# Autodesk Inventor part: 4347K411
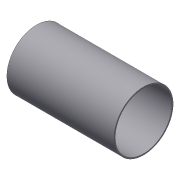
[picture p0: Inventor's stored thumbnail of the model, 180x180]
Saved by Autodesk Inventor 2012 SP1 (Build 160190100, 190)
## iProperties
Created: 2012-02
Part Number: 4347K411
Material: Aluminum-6061
Document SubType Name: Modeling
Designer: LACO
Density: 2.71 g/cm^3
Mass: 1456.19 g
Surface Area: 3192.74 cm^2
Volume: 537.339 cm^3
Translation Standard: STEP AP203
FileName: 4347K411.step
PreProcessor: SolidWorks 2009
PostProcessor: Build: 190, Release: 2012 SP1 - Date: Mon 08/08/2011
Sent Units: inch
Uncertainty: 1e-05
Author: LACO
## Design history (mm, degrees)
node "4347K4111"
node "NONE"
node "Base1"
